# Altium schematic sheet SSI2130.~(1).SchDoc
size Letter
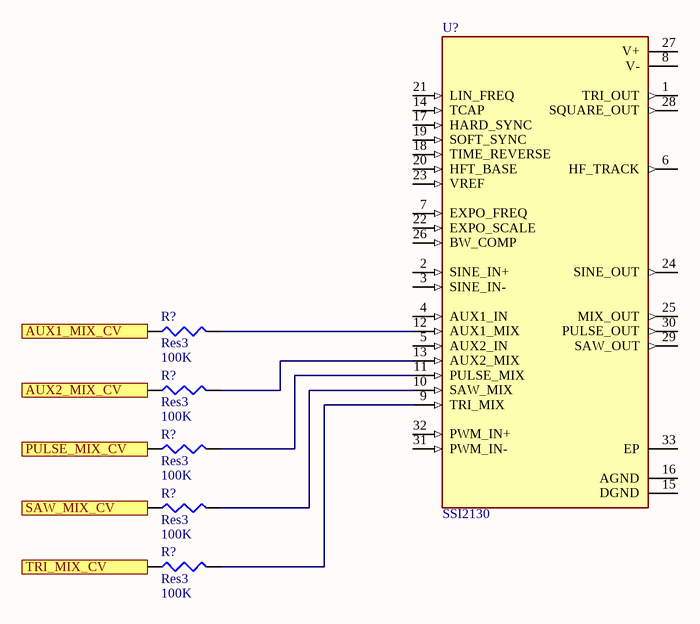
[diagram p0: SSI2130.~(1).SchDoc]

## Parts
(Parts that share a designator on the sheet are numbered #1, #2 ... from top to bottom, then left to right.)
R?#1  Res3  value 100K  [J1-0603]
R?#2  Res3  value 100K  [J1-0603]
R?#3  Res3  value 100K  [J1-0603]
R?#4  Res3  value 100K  [J1-0603]
R?#5  Res3  value 100K  [J1-0603]
U?  SSI2130  [QFN40P400X400X90-33N]

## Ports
AUX1_MIX_CV, AUX2_MIX_CV, PULSE_MIX_CV, SAW_MIX_CV, TRI_MIX_CV

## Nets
AUX1_MIX_CV: R?#1.1 ; port AUX1_MIX_CV
AUX2_MIX_CV: R?#2.1 ; port AUX2_MIX_CV
PULSE_MIX_CV: R?#3.1 ; port PULSE_MIX_CV
SAW_MIX_CV: R?#4.1 ; port SAW_MIX_CV
TRI_MIX_CV: R?#5.1 ; port TRI_MIX_CV
NetR?#1_2: R?#1.2 U?.12(AUX1_MIX)
NetR?#2_2: R?#2.2 U?.13(AUX2_MIX)
NetR?#3_2: R?#3.2 U?.11(PULSE_MIX)
NetR?#4_2: R?#4.2 U?.10(SAW_MIX)
NetR?#5_2: R?#5.2 U?.9(TRI_MIX)

Not connected (* = marked no-connect by the designer): U? 1(TRI_OUT) 2(SINE_IN+) 3(SINE_IN-) 4(AUX1_IN) 5(AUX2_IN) 6(HF_TRACK) 7(EXPO_FREQ) 8(V-) 14(TCAP) 15(DGND) 16(AGND) 17(HARD_SYNC) 18(TIME_REVERSE) 19(SOFT_SYNC) 20(HFT_BASE) 21(LIN_FREQ) 22(EXPO_SCALE) 23(VREF) 24(SINE_OUT) 25(MIX_OUT) 26(BW_COMP) 27(V+) 28(SQUARE_OUT) 29(SAW_OUT) 30(PULSE_OUT) 31(PWM_IN-) 32(PWM_IN+) 33(EP)

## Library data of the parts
R?#1-R?#5 = Res3: Resistor
U? = SSI2130: Voltage controlled oscillator subsystem for high-performance electronic musical instruments; MF: Sound Semiconductor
